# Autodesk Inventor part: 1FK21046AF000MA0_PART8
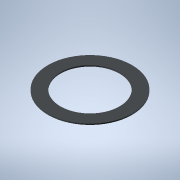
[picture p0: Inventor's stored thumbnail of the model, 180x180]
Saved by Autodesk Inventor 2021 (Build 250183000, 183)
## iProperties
Created: 2025-04
Part Number: 1FK21046AF000MA0_PART8
Material: Generic
Catalog Web Link: www.3dfindit.com
Description: -Servo synchronous motor
Document SubType Name: Modeling
Designer: psAdmin
Mass: 0.27214 g
Surface Area: 11.8752 cm^2
Volume: 0.27214 cm^3
Density: 1 g/cm^3
Appearance: PSOLRGB-212-217-219
Category: PARTsolutions
Title: 1FK21046AF000MA0_PART8
Author: Cadenas PARTsolutions
Comments: Servo synchronous motor
Sending System: PARTsolutions
Preprocessor: ST-DEVELOPER v19.3
PSOL_IDENT_0: {$CADENAS_DATA/23d-libs/siemens_ag/_cat_/1c/1f/1fk21046af000ma0.prj},213 {VTYP=3D},{NB=1FK21046AF000
PSOL_IDENT_1: MA0_PART8},{LINA=1FK21046AF000MA0_PART8},{NN=1FK21046AF000MA0_PART8},{NOPRJ=TRUE},{DATE=19.08.2025 1
PSOL_IDENT_2: 4:00:28},{GEOMDATE=30.07.2025 02:02:08},{VERSION=},{LINEID=10},{WBVAR=},{WBNUMERIC=}  {NB=1FK21046AF
PSOL_IDENT_3: 000MA0_PART8},{LINA=1FK21046AF000MA0_PART8},{KT=DUMMY},{PREVIEW=../../../_pool_/cb/72/p_d211_xx_0043
PSOL_IDENT_4: 4j.png},{DESCSHORT=SIMOTICS S-1FK2 HD, SINAMICS S210 3AC 400V-480V, 3.2 Nm, 3000 rpm},{DESCLONG=SIMO
PSOL_IDENT_5: TICS S-1FK2 HD servo motor M0=3.2 Nm; PN = 1 kW at nN=3000 rpm (380-480 V); PN = 0.5 kW at nN=1500 r
PSOL_IDENT_6: pm (200-240 V); degree of protection IP64; cylindrical shaft D19x40mm; absolute encoder 22-bit + 12-
PSOL_IDENT_7: bit multiturn (encoder AM22DQC); with OCC interface; plug size M17, rotatable; SIMOTICS S-1FK2 servo
PSOL_IDENT_8: motorfor a wide range of uses in industrial environments. SIMOTICS S‑1FK2 servomotors are compact sy
PSOL_IDENT_9: nchronous motors with a high dynamic performance that set themselves apart as a result of their high
PSOL_IDENT_10: power density, degree of protection and overload capability. The motors are available in two varian
PSOL_IDENT_11: ts: as High Dynamic variant (highest dynamic performance as a result of the low intrinsic moment of
PSOL_IDENT_12: inertia for applications demanding a high dynamic performance with low moved masses) - and as Compac
PSOL_IDENT_13: t variant (precise and stable closed-loop control for medium up to large moved masses as a result of
PSOL_IDENT_14: a medium intrinsic moment of inertia). SIMOTICSS‑1FK2 servomotors fully exploit their strengths in
PSOL_IDENT_15: a system with the SINAMICSS210 frequency converter and simple connection using the one cable connect
PSOL_IDENT_16: ion (OCC). Advantages include the short control and positioning times, fast and precise correction o
PSOL_IDENT_17: f disturbing quantities as well as stable control with a high dynamic performance. The servo motors
PSOL_IDENT_18: can be configured to address a wide range of requirements. For example with and without holding brak
PSOL_IDENT_19: e, IP64 or IP65 degree of protection, singleturn or multiturn absolute encoders - to name just a few
PSOL_IDENT_20: . Further, the servomotors are available in different shaft heights extending from 20 to 100. A shaf
PSOL_IDENT_21: t sealing ring is available to achieve an IP65 degree of protection and for subsequent mounting at t
PSOL_IDENT_22: he motor or as spare part. SIMOTICS - the optimum motor for each and every motion control applicatio
PSOL_IDENT_23: n.},{INTNO=195125049666},{SUPPLIERALTNO=1FK2104-6AF00-0MA0},{MANUID=1FK21046AF000MA0},{MANUNAME=Siem
PSOL_IDENT_24: ens},{MANUTYPEDESC=Synchronous motor 1FK2-HD 3.2 NM},{AAU732=SIMOTICS},{AAO057=S-1FK2},{AAU734=SIMOT
PSOL_IDENT_25: ICS S-1FK2 HD servo motor M0=3.2 Nm; PN = 1 kW at nN=3000 rpm (380-480 V); PN = 0.5 kW at nN=1500 rp
PSOL_IDENT_26: m (200-240 V); degree of protection IP64; cylindrical shaft D19x40mm; absolute encoder 22-bit + 12-b
PSOL_IDENT_27: it multiturn (encoder AM22DQC); with OCC interface; plug size M17, rotatable;},{AAW338=Synchronous m
PSOL_IDENT_28: otor 1FK2-HD 3.2 NM},{AAO742=SIMOTICS},{AAO663=4042948694374},{NOCUPEROU=1},{PRICEQUANTITY=1},{QUANT
PSOL_IDENT_29: ITYMIN=1},{QUANTITYINT=1},{CTN=85015220},{COO=DE},{AAO676=1FK2104-6AF00-0MA0},{AAO677=Siemens AG},{O
PSOL_IDENT_30: RDERUNIT=C62},{CONTENTUNIT=C62}
NB: 1FK21046AF000MA0_PART8
NT: Servo synchronous motor
NBSYN: $MANUID._PART8
LINA: 1FK21046AF000MA0_PART8
CATALOG: SIEMENS
PREVIEW: ../../../_pool_/cb/72/p_d211_xx_00434j.png
DESCSHORT: SIMOTICS S-1FK2 HD, SINAMICS S210 3AC 400V-480V, 3.2 Nm, 3000 rpm
DESCLONG: SIMOTICS S-1FK2 HD servo motor M0=3.2 Nm; PN = 1 kW at nN=3000 rpm (380-480 V); PN = 0.5 kW at nN=1500 rpm (200-240 V); degree of protection IP64; cylindrical s
INTNO: 195125049666
SUPPLIERALTNO: 1FK2104-6AF00-0MA0
MANUID: 1FK21046AF000MA0
MANUNAME: Siemens
MANUTYPEDESC: Synchronous motor 1FK2-HD 3.2 NM
AAU732: SIMOTICS
AAO057: S-1FK2
AAU734: SIMOTICS S-1FK2 HD servo motor M0=3.2 Nm; PN = 1 kW at nN=3000 rpm (380-480 V); PN = 0.5 kW at nN=1500 rpm (200-240 V); degree of protection IP64; cylindrical s
AAW338: Synchronous motor 1FK2-HD 3.2 NM
AAO742: SIMOTICS
AAO663: 4042948694374.0
NOCUPEROU: 1
PRICEQUANTITY: 1
QUANTITYMIN: 1
QUANTITYINT: 1
CTN: 85015220
COO: DE
ARTICLENO: 1FK21046AF000MA0_PART8
BOMINFO: 1FK21046AF000MA0_PART8
CREATOR: CADENAS GmbH
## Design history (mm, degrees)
feature "2025_04_17_15_39_11_0412"
body "Solid1"
